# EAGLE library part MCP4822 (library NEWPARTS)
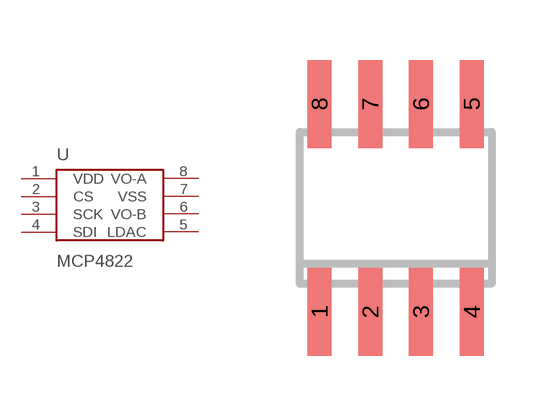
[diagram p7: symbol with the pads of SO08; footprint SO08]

Designator prefix -

## MCP4822  [SO08]
1  VDD
2  CS
3  SCK
4  SDI
5  LDAC
6  VO-B
7  VSS
8  VO-A

## Footprint SO08 (pad centres in mm)
Small Outline Package 8 NS Package M08A
smd 0.6 x 2.2: 1 -1.905,-2.6; 2 -0.635,-2.6; 3 0.635,-2.6; 4 1.905,-2.6; 5 1.905,2.6; 6 0.635,2.6; 7 -0.635,2.6; 8 -1.905,2.6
